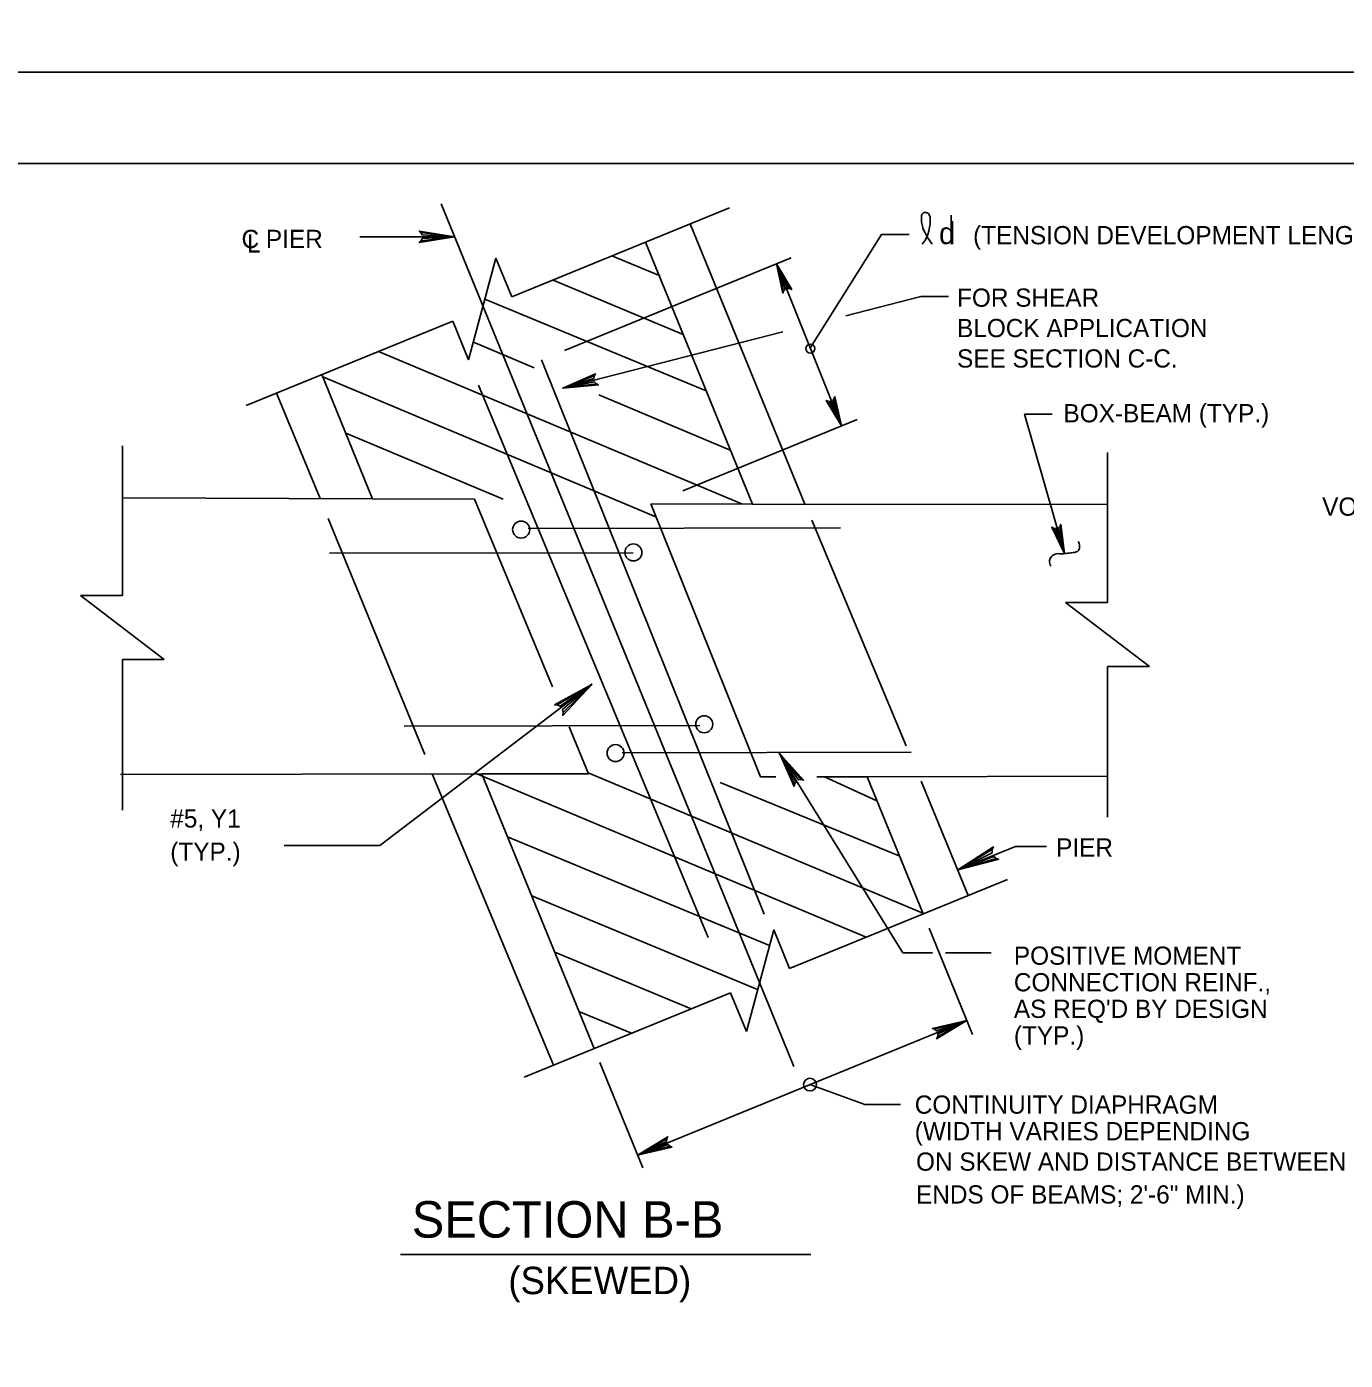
# Model space of a CAD drawing. Extents: x 641517 to 642372, y 298537 to 300319.
# Drawn here: x 641864.7 to 642081.6, y 299512.8 to 299732.1 of the extents above; entities that cross this region are included whole.
import ezdxf

# ---------------------------------------------------------------- set-up
doc = ezdxf.new("R2010")
doc.units = 0
for name, color, linetype in [('1', 7, 'Continuous'), ('2', 7, 'Continuous'), ('3', 7, 'Continuous'), ('PLT-BNDY', 7, 'Continuous')]:
    doc.layers.add(name, color=color, linetype=linetype)

msp = doc.modelspace()

# ---------------------------------------------------------------- linework, layer by layer
at = {"layer": '1'}
msp.add_spline([(642033.14, 299643.4), (642032.94, 299644.35), (642033.27, 299644.99), (642034.09, 299645.45), (642034.99, 299645.44), (642035.91, 299645.53), (642036.84, 299645.64), (642037.68, 299645.99), (642037.87, 299646.75), (642037.66, 299647.46)], degree=3, dxfattribs=at)
at = {"layer": '2'}
for p, q in [((641557.05, 299709.62), (642343.05, 299709.62)), ((641990.86, 299561.14), (641932.84, 299702.99)), ((641980.3, 299702.34), (641944.46, 299687.68)), ((642012.76, 299701.54), (642012.75, 299701.54)), ((642013.27, 299700.89), (642013.16, 299701.14)), ((642016.74, 299696.35), (642016.74, 299701.12)), ((641992.67, 299653.6), (641973.82, 299699.69)), ((642011.85, 299700.82), (642011.86, 299700.13)), ((642011.88, 299699.98), (642012.08, 299699.12)), ((642012.11, 299699), (642012.41, 299698.27)), ((642013.07, 299698.56), (642013.29, 299699.65)), ((642013.31, 299699.78), (642013.32, 299700.59)), ((641935.06, 299697.58), (641919.45, 299697.58)), ((641984.06, 299653.62), (641966.44, 299696.67)), ((642005.31, 299697.94), (641993.61, 299679.36)), ((642009.84, 299697.94), (642005.31, 299697.94)), ((642011.98, 299696.36), (642012.39, 299696.85)), ((642012.45, 299698.2), (642012.92, 299697.34)), ((642012.47, 299696.98), (642012.72, 299697.43)), ((642012.78, 299697.57), (642013.06, 299698.49)), ((642012.96, 299697.28), (642013.6, 299696.36)), ((641941.85, 299694.07), (641937.36, 299677.32)), ((641941.85, 299694.07), (641944.46, 299687.68)), ((641990.42, 299694.11), (641953.13, 299678.86)), ((641988, 299693.12), (641998.71, 299666.47)), ((642011.76, 299687.74), (641999.42, 299684.59)), ((642016.29, 299687.74), (642011.76, 299687.74)), ((641934.74, 299683.71), (641900.79, 299669.82)), ((641934.74, 299683.71), (641937.36, 299677.32)), ((641989.06, 299681.95), (641952.84, 299672.7)), ((641949.38, 299677.33), (641986.01, 299586.18)), ((641913.22, 299674.91), (641921.52, 299654.62)), ((641939, 299673.16), (641976.8, 299582.34)), ((641905.76, 299671.86), (641912.96, 299654.53)), ((642033.35, 299668.39), (642028.82, 299668.39)), ((642028.82, 299668.39), (642035.39, 299645.48)), ((642001.3, 299667.52), (641972.58, 299655.78)), ((641880.4, 299663.22), (641880.4, 299638.57)), ((642042.47, 299662.09), (642042.47, 299637.44)), ((641921.52, 299654.5), (641880.4, 299654.67)), ((641938.31, 299654.43), (641921.57, 299654.5)), ((641938.31, 299654.43), (641951.16, 299623.55)), ((641967.35, 299653.64), (641985.38, 299608.77)), ((641984.06, 299653.62), (641967.35, 299653.64)), ((642042.47, 299653.53), (641984.06, 299653.62)), ((641930.14, 299612.42), (641914.25, 299651.27)), ((642009.34, 299613.87), (641993.84, 299650.98)), ((641947.14, 299649.63), (641998.54, 299649.73)), ((641964.41, 299645.63), (641914.46, 299645.53)), ((641873.5, 299638.57), (641880.4, 299638.57)), ((641873.5, 299638.57), (641887.3, 299628.07)), ((642035.57, 299637.44), (642042.47, 299637.44)), ((642035.57, 299637.44), (642049.37, 299626.94)), ((641880.4, 299628.07), (641880.4, 299603.29)), ((641880.4, 299628.07), (641887.3, 299628.07)), ((642042.47, 299626.94), (642042.47, 299602.15)), ((642042.47, 299626.94), (642049.37, 299626.94)), ((641922.75, 299597.51), (641957.69, 299624.05)), ((641975.38, 299617.23), (641926.77, 299617.13)), ((641953.89, 299616.99), (641957.1, 299609.28)), ((641962.6, 299612.72), (642010.15, 299612.82)), ((642008.79, 299579.86), (641988.41, 299612.77)), ((641880.1, 299609.17), (641939.61, 299609.25)), ((641931.38, 299609.24), (641951.31, 299561.35)), ((641939.54, 299609.25), (641957.1, 299609.28)), ((641939.61, 299609.08), (641958.01, 299564.09)), ((641985.38, 299608.77), (641987.89, 299608.77)), ((641994.66, 299608.79), (642002.92, 299608.8)), ((642002.92, 299608.8), (642042.47, 299608.88)), ((642012.15, 299586.23), (642002.92, 299608.8)), ((642019.53, 299589.25), (642011.84, 299608.06)), ((641907, 299597.51), (641922.75, 299597.51)), ((642027.32, 299597.32), (642017.86, 299593.46)), ((642032.46, 299597.32), (642027.32, 299597.32)), ((642026.01, 299591.9), (641990.17, 299577.24)), ((641987.56, 299583.63), (641983.06, 299566.88)), ((641987.56, 299583.63), (641990.17, 299577.24)), ((642020.27, 299566.4), (642013.11, 299583.89)), ((642013.7, 299579.86), (642008.79, 299579.86)), ((642023.35, 299579.86), (642015.8, 299579.86)), ((641980.45, 299573.27), (641946.5, 299559.39)), ((641980.45, 299573.27), (641983.06, 299566.88)), ((641965.17, 299546.58), (642019.31, 299568.72)), ((641966.04, 299544.46), (641958.94, 299561.82)), ((642002.57, 299554.9), (641993.52, 299558.17)), ((642008.4, 299554.9), (642002.57, 299554.9)), ((641993.67, 299530.25), (641926.17, 299530.25))]:
    msp.add_line(p, q, dxfattribs=at)
for points in [[(642012.25, 299701.55), (642012.19, 299701.54), (642011.99, 299701.27)], [(641929.52, 299698.27), (641929.73, 299697.87), (641935.06, 299697.58), (641929.52, 299698.27), (641929.24, 299698.52), (641935.06, 299697.58), (641929.73, 299697.31), (641929.54, 299696.92), (641935.06, 299697.58), (641929.24, 299696.65), (641929.54, 299696.92)], [(641960.93, 299694.42), (641968.85, 299691.13)], [(641989.18, 299688.62), (641989.43, 299688.91), (641988, 299693.12), (641989.18, 299688.62), (641989.08, 299688.33), (641988, 299693.12), (641989.86, 299689.08), (641990.22, 299689.06), (641988, 299693.12), (641990.52, 299688.91), (641990.22, 299689.06)], [(641951.25, 299690.46), (641972.66, 299681.48)], [(641940.04, 299687.31), (641976.44, 299672.23)], [(641938.14, 299680.24), (641948.15, 299676.04)], [(641922.56, 299678.73), (641982.42, 299653.62)], [(641958.38, 299673.39), (641958.08, 299673.73), (641952.84, 299672.7), (641958.38, 299673.39), (641958.71, 299673.23), (641952.84, 299672.7), (641957.94, 299674.27), (641958.03, 299674.7), (641952.84, 299672.7), (641958.25, 299675.03), (641958.03, 299674.7)], [(641913.38, 299674.52), (641968.19, 299651.53)], [(641958.79, 299671.58), (641980.42, 299662.51)], [(641997.53, 299670.96), (641997.28, 299670.68), (641998.71, 299666.47), (641997.53, 299670.96), (641997.63, 299671.26), (641998.71, 299666.47), (641996.85, 299670.5), (641996.48, 299670.53), (641998.71, 299666.47), (641996.19, 299670.68), (641996.48, 299670.53)], [(641917.17, 299665.27), (641943.06, 299654.41)], [(641938.74, 299609.25), (642002.77, 299582.4)], [(641957.03, 299609.44), (642012.11, 299586.34)], [(641978.73, 299607.85), (642008.28, 299595.71)], [(641995.93, 299608.79), (642004.54, 299604.85)], [(641943.77, 299598.9), (641986.86, 299581.04)], [(641947.74, 299589.18), (641984.91, 299573.78)], [(641951.53, 299579.93), (641973.98, 299570.62)], [(641955.51, 299570.21), (641964.18, 299566.61)]]:
    msp.add_lwpolyline(points, dxfattribs=at)
for centre, radius in [((641993.58, 299679.2), 0.739), ((641946.01, 299649.42), 1.4), ((641964.47, 299645.67), 1.4), ((641976.12, 299617.41), 1.4), ((641961.53, 299612.68), 1.4), ((641993.52, 299558.17), 1.05)]:
    msp.add_circle(centre, radius, dxfattribs=at)
for centre, start, end in [((642012.58, 299700.84), 142.942, 181.1567), ((642012.48, 299700.86), 68.3745, 108.4443), ((642012.49, 299700.86), 22.4358, 68.3745), ((642012.59, 299700.14), 181.1567, 192.772), ((642012.79, 299699.28), 192.772, 202.4051), ((642012.59, 299700.61), 358.8549, 22.4358), ((642012.58, 299699.8), 348.6689, 358.8549), ((642011.83, 299697.32), 319.6823, 331.4731), ((642013.09, 299698.55), 202.4051, 209.0413), ((642012.08, 299697.78), 331.4731, 343.3094), ((642013.56, 299697.7), 209.0413, 214.8098), ((642012.36, 299698.7), 343.3094, 348.6689)]:
    msp.add_arc(centre, 0.729, start, end, dxfattribs=at)
at = {"layer": '3'}
for points in [[(642034.66, 299650), (642034.39, 299649.74), (642035.39, 299645.48), (642034.66, 299650), (642034.79, 299650.27), (642035.39, 299645.48), (642033.95, 299649.61), (642033.6, 299649.67), (642035.39, 299645.48), (642033.32, 299649.85), (642033.6, 299649.67)], [(641951.94, 299620.59), (641952.42, 299620.37), (641957.62, 299623.94), (641951.94, 299620.59), (641951.5, 299620.61), (641957.62, 299623.94), (641952.83, 299619.85), (641952.94, 299619.34), (641957.62, 299623.94), (641952.85, 299618.87), (641952.94, 299619.34)], [(641990.97, 299607.57), (641991.19, 299607.96), (641988.59, 299612.53), (641990.97, 299607.57), (641990.92, 299607.21), (641988.59, 299612.53), (641991.65, 299608.26), (641992.08, 299608.31), (641988.59, 299612.53), (641992.46, 299608.2), (641992.08, 299608.31)], [(642024.17, 299595.36), (642023.75, 299595.7), (642017.86, 299593.46), (642024.17, 299595.36), (642024.59, 299595.24), (642017.86, 299593.46), (642023.48, 299596.3), (642023.5, 299596.82), (642017.86, 299593.46), (642023.7, 299597.25), (642023.5, 299596.82)], [(642014.01, 299567.28), (642014.35, 299567), (642019.32, 299568.72), (642014.01, 299567.28), (642013.67, 299567.4), (642019.32, 299568.72), (642014.57, 299566.49), (642014.54, 299566.06), (642019.32, 299568.72), (642014.36, 299565.7), (642014.54, 299566.06)], [(641970.47, 299548.02), (641970.13, 299548.31), (641965.17, 299546.58), (641970.47, 299548.02), (641970.82, 299547.9), (641965.17, 299546.58), (641969.92, 299548.81), (641969.95, 299549.25), (641965.17, 299546.58), (641970.12, 299549.6), (641969.95, 299549.25)]]:
    msp.add_lwpolyline(points, dxfattribs=at)
at = {"layer": 'PLT-BNDY'}
for points in [[(641517.05, 300318.62), (642358.05, 300318.62), (642358.05, 299724.62), (641517.05, 299724.62)], [(641517.05, 299724.62), (642358.05, 299724.62), (642358.05, 299130.62), (641517.05, 299130.62)]]:
    msp.add_lwpolyline(points, close=True, dxfattribs=at)

# ---------------------------------------------------------------- texts
at = {"layer": '2'}
for s, height, p in [('d', 3.6, (642014.75, 299696.36)), ('(TENSION DEVELOPMENT LENGTH, TYP.)', 3, (642020.36, 299696.34)), ('SECTION B-B', 6, (641928.01, 299533))]:
    msp.add_text(s, height=height, dxfattribs=at).set_placement(p)
at = {"layer": '3'}
for s, height, p in [('C PIER', 2.999, (641900, 299695.72)), ('L', 3, (641900.9, 299694.99)), ('FOR SHEAR', 2.997, (642017.72, 299686.07)), ('BLOCK APPLICATION', 2.9969, (642017.72, 299681.07)), ('SEE SECTION C-C.', 2.9969, (642017.72, 299676.07)), ('BOX-BEAM (TYP.)', 2.9969, (642035.23, 299667.07)), ('VOID (TYP.)', 2.9968, (642077.79, 299651.71)), ('#5, Y1', 2.997, (641888.28, 299600.43)), ('(TYP.)', 2.997, (641888.28, 299594.97)), ('PIER', 2.997, (642034.02, 299595.67)), ('POSITIVE MOMENT', 2.9969, (642027.07, 299577.87)), ('CONNECTION REINF.,', 2.9969, (642027.07, 299573.5)), ("AS REQ'D BY DESIGN", 2.9969, (642027.07, 299569.13)), ('(TYP.)', 2.997, (642027.07, 299564.76)), ('CONTINUITY DIAPHRAGM', 2.9969, (642010.76, 299553.38)), ('(WIDTH VARIES DEPENDING', 2.9969, (642010.76, 299549.01)), ('ON SKEW AND DISTANCE BETWEEN', 2.9969, (642010.97, 299544.01)), ('ENDS OF BEAMS; 2\'-6" MIN.)', 2.9969, (642010.97, 299538.61)), ('(SKEWED)', 4.5, (641943.9, 299523.71))]:
    msp.add_text(s, height=height, dxfattribs=at).set_placement(p)

doc.saveas('drawing.dxf')
